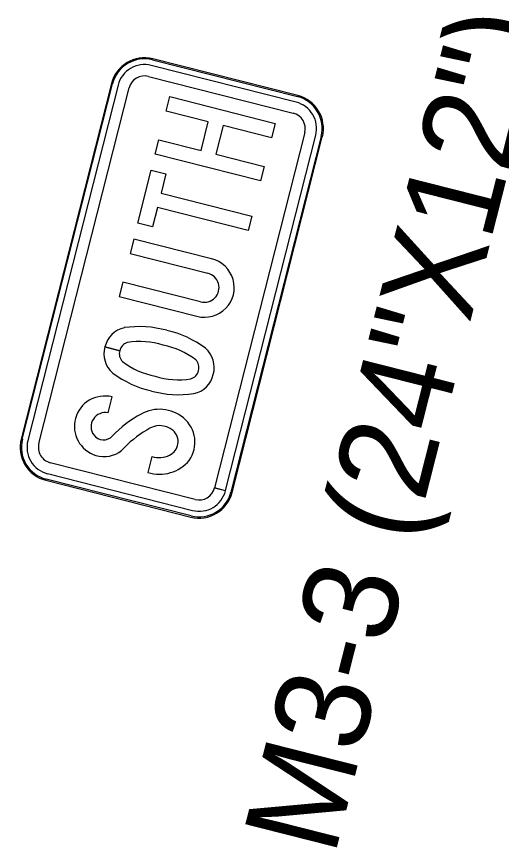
# Model space of a CAD drawing. Extents: x 670257 to 671518, y 737783 to 738188.
# Drawn here: x 670267.544 to 670268.827, y 738167.909 to 738170.109 of the extents above; entities that cross this region are included whole.
import ezdxf

# ---------------------------------------------------------------- set-up
doc = ezdxf.new("R2010")
doc.units = 0
doc.layers.add('R_SIGN_ANNOT', color=7, linetype='Continuous')
doc.layers.add('R_SIGN_HWY102', color=7, linetype='Continuous')

msp = doc.modelspace()

# ---------------------------------------------------------------- linework, layer by layer
at = {"layer": 'R_SIGN_HWY102'}
for p, q in [((670267.9, 738169.9798), (670267.8999, 738169.9798)), ((670268.2836, 738169.8825), (670267.9, 738169.9798)), ((670267.9036, 738169.9943), (670267.9036, 738169.9943)), ((670267.9036, 738169.9943), (670268.2873, 738169.897)), ((670268.288, 738169.8999), (670267.9044, 738169.9972)), ((670267.9044, 738169.9972), (670267.9044, 738169.9972)), ((670268.288, 738169.8999), (670267.9044, 738169.9972)), ((670267.9044, 738169.9972), (670267.9044, 738169.9972)), ((670267.8926, 738169.9507), (670267.8926, 738169.9507)), ((670267.8926, 738169.9507), (670268.2762, 738169.8534)), ((670267.7951, 738169.9321), (670267.5562, 738168.9903)), ((670267.7951, 738169.9321), (670267.5562, 738168.9903)), ((670267.5591, 738168.9896), (670267.798, 738169.9314)), ((670267.8125, 738169.9277), (670267.5737, 738168.9859)), ((670267.6027, 738168.9785), (670267.8416, 738169.9203)), ((670267.7951, 738169.9321), (670267.7951, 738169.9321)), ((670267.7951, 738169.9321), (670267.7951, 738169.9321)), ((670267.798, 738169.9314), (670267.798, 738169.9314)), ((670267.8125, 738169.9277), (670267.8125, 738169.9277)), ((670267.8416, 738169.9203), (670267.8416, 738169.9203)), ((670268.2873, 738169.897), (670268.2873, 738169.897)), ((670268.288, 738169.8999), (670268.288, 738169.8999)), ((670268.288, 738169.8999), (670268.288, 738169.8999)), ((670268.2836, 738169.8825), (670268.2836, 738169.8825)), ((670268.2762, 738169.8534), (670268.2762, 738169.8534)), ((670268.3066, 738169.8024), (670268.0678, 738168.8609)), ((670268.3066, 738169.8024), (670268.3066, 738169.8024)), ((670268.0968, 738168.8535), (670268.3356, 738169.795)), ((670268.3501, 738169.7913), (670268.1113, 738168.8496)), ((670268.1142, 738168.8488), (670268.353, 738169.7906)), ((670268.1142, 738168.8489), (670268.353, 738169.7906)), ((670268.3356, 738169.795), (670268.3356, 738169.795)), ((670268.3501, 738169.7913), (670268.3501, 738169.7913)), ((670268.353, 738169.7906), (670268.353, 738169.7906)), ((670268.353, 738169.7906), (670268.353, 738169.7906)), ((670267.8152, 738169.3674), (670268.0209, 738169.3152)), ((670267.8152, 738169.3674), (670268.0209, 738169.3152)), ((670267.8152, 738169.3674), (670268.0209, 738169.3152)), ((670267.8171, 738169.2242), (670267.7778, 738169.2342)), ((670267.7778, 738169.2342), (670267.8171, 738169.2242)), ((670267.8171, 738169.2242), (670267.7778, 738169.2342)), ((670267.7778, 738169.2342), (670267.8171, 738169.2242)), ((670267.7861, 738169.06), (670267.7967, 738169.1019)), ((670267.7861, 738169.06), (670267.7967, 738169.1019)), ((670267.7861, 738169.06), (670267.7967, 738169.1019)), ((670267.5562, 738168.9903), (670267.5562, 738168.9903)), ((670267.5562, 738168.9903), (670267.5562, 738168.9903)), ((670267.5591, 738168.9896), (670267.5591, 738168.9896)), ((670267.5737, 738168.9859), (670267.5737, 738168.9859)), ((670267.6027, 738168.9785), (670267.6027, 738168.9785)), ((670268.0167, 738168.8302), (670267.6331, 738168.9275)), ((670267.6331, 738168.9275), (670267.6331, 738168.9275)), ((670267.9022, 738168.944), (670267.8915, 738168.9014)), ((670267.9022, 738168.944), (670267.8915, 738168.9014)), ((670267.9022, 738168.944), (670267.8915, 738168.9014)), ((670267.6213, 738168.881), (670267.6213, 738168.881)), ((670267.6213, 738168.881), (670268.0049, 738168.7837)), ((670267.6213, 738168.881), (670267.6213, 738168.881)), ((670267.6213, 738168.881), (670268.0049, 738168.7837)), ((670268.0056, 738168.7866), (670267.622, 738168.884)), ((670267.622, 738168.884), (670267.622, 738168.8839)), ((670267.6257, 738168.8985), (670267.6257, 738168.8985)), ((670267.6257, 738168.8985), (670268.0093, 738168.8012)), ((670268.0967, 738168.8532), (670268.0677, 738168.8606)), ((670268.0677, 738168.8606), (670268.0677, 738168.8606)), ((670268.0678, 738168.8609), (670268.0968, 738168.8535)), ((670268.0967, 738168.8532), (670268.0967, 738168.8532)), ((670268.1142, 738168.8488), (670268.1113, 738168.8496)), ((670268.1113, 738168.8496), (670268.1113, 738168.8496)), ((670268.1113, 738168.8496), (670268.1142, 738168.8489)), ((670268.1142, 738168.8488), (670268.1142, 738168.8488)), ((670268.0167, 738168.8302), (670268.0167, 738168.8302)), ((670268.0093, 738168.8012), (670268.0093, 738168.8012)), ((670268.0049, 738168.7837), (670268.0049, 738168.7837)), ((670268.0049, 738168.7837), (670268.0049, 738168.7837)), ((670268.0056, 738168.7866), (670268.0056, 738168.7866))]:
    msp.add_line(p, q, dxfattribs=at)
for points in [[(670267.9108, 738169.7445), (670267.9206, 738169.7829), (670268.0322, 738169.7546), (670268.0513, 738169.8302), (670267.9398, 738169.8585), (670267.9495, 738169.897), (670268.2285, 738169.8263), (670268.2187, 738169.7878), (670268.0904, 738169.8203), (670268.0712, 738169.7447), (670268.1995, 738169.7122), (670268.1898, 738169.6737)], [(670267.9108, 738169.7445), (670267.9206, 738169.7829), (670268.0322, 738169.7546), (670268.0513, 738169.8302), (670267.9398, 738169.8585), (670267.9495, 738169.897), (670268.2285, 738169.8263), (670268.2187, 738169.7878), (670268.0904, 738169.8203), (670268.0712, 738169.7447), (670268.1995, 738169.7122), (670268.1898, 738169.6737)], [(670267.9108, 738169.7445), (670267.9206, 738169.7829), (670268.0322, 738169.7546), (670268.0513, 738169.8302), (670267.9398, 738169.8585), (670267.9495, 738169.897), (670268.2285, 738169.8263), (670268.2187, 738169.7878), (670268.0904, 738169.8203), (670268.0712, 738169.7447), (670268.1995, 738169.7122), (670268.1898, 738169.6737)], [(670267.9165, 738169.603), (670267.9036, 738169.5522), (670267.8646, 738169.5621), (670267.9001, 738169.7022), (670267.9392, 738169.6923), (670267.9263, 738169.6415), (670268.1662, 738169.5807), (670268.1564, 738169.5421)], [(670267.9165, 738169.603), (670267.9036, 738169.5522), (670267.8646, 738169.5621), (670267.9001, 738169.7022), (670267.9392, 738169.6923), (670267.9263, 738169.6415), (670268.1662, 738169.5807), (670268.1564, 738169.5421)], [(670267.9165, 738169.603), (670267.9036, 738169.5522), (670267.8646, 738169.5621), (670267.9001, 738169.7022), (670267.9392, 738169.6923), (670267.9263, 738169.6415), (670268.1662, 738169.5807), (670268.1564, 738169.5421)]]:
    msp.add_lwpolyline(points, close=True, dxfattribs=at)
for points in [[(670268.0596, 738169.4677), (670267.8539, 738169.5199), (670267.8441, 738169.4815), (670268.0498, 738169.4293)], [(670268.0596, 738169.4677), (670267.8539, 738169.5199), (670267.8441, 738169.4815), (670268.0498, 738169.4293)], [(670268.0596, 738169.4677), (670267.8539, 738169.5199), (670267.8441, 738169.4815), (670268.0498, 738169.4293)], [(670268.0307, 738169.3537), (670267.8249, 738169.4058), (670267.8152, 738169.3674)], [(670268.0307, 738169.3537), (670267.8249, 738169.4058), (670267.8152, 738169.3674)], [(670268.0307, 738169.3537), (670267.8249, 738169.4058), (670267.8152, 738169.3674)]]:
    msp.add_lwpolyline(points, dxfattribs=at)
for centre, major_axis, ratio, start_param, end_param in [((670267.8823, 738169.91), (0.0221, 0.0872), 0.999584, 0, 1.570796), ((670267.8823, 738169.91), (0.0221, 0.0872), 0.999584, 0, 1.570796), ((670267.8823, 738169.91), (0.0214, 0.0843), 0.999584, 0, 1.570796), ((670267.8823, 738169.91), (0.0177, 0.0698), 0.999584, 0, 1.570796), ((670267.8823, 738169.91), (0.0103, 0.0407), 0.999584, 0, 1.570796), ((670268.2659, 738169.8127), (0.0214, 0.0843), 0.999584, 4.712389, 6.283185), ((670268.2659, 738169.8127), (0.0221, 0.0872), 0.999584, 4.712389, 6.283185), ((670268.2659, 738169.8127), (0.0221, 0.0872), 0.999584, 4.712389, 6.283185), ((670268.2659, 738169.8127), (0.0177, 0.0698), 0.999584, 4.712389, 6.283185), ((670268.2659, 738169.8127), (0.0103, 0.0407), 0.999584, 4.712389, 6.283185), ((670268.0402, 738169.3915), (-0.0774, 0.0196), 0.985401, 1.570796, 4.712389), ((670268.0402, 738169.3915), (-0.0774, 0.0196), 0.985401, 1.570796, 4.712389), ((670268.0402, 738169.3915), (-0.0774, 0.0196), 0.985401, 1.570796, 4.712389), ((670268.0402, 738169.3915), (-0.0384, 0.0097), 0.985401, 1.570796, 4.712389), ((670268.0402, 738169.3915), (-0.0384, 0.0097), 0.985401, 1.570796, 4.712389), ((670268.0402, 738169.3915), (-0.0384, 0.0097), 0.985401, 1.570796, 4.712389), ((670267.8441, 738169.2197), (-0.0657, 0.0167), 0.987317, 5.182411, 6.318105), ((670267.8441, 738169.2197), (-0.0657, 0.0167), 0.987317, 5.182411, 6.317893), ((670267.8441, 738169.2197), (-0.0657, 0.0167), 0.987317, 5.182411, 6.317893), ((670267.87, 738169.0184), (-0.2645, 0.0671), 0.987317, 4.692766, 5.109028), ((670267.87, 738169.0184), (-0.2645, 0.0671), 0.987317, 4.692766, 5.109028), ((670267.87, 738169.0184), (-0.2645, 0.0671), 0.987317, 4.692766, 5.109028), ((670267.8804, 738169.0157), (-0.2645, 0.0671), 0.987317, 4.31575, 4.732012), ((670267.8804, 738169.0157), (-0.2645, 0.0671), 0.987317, 4.31575, 4.732012), ((670267.8804, 738169.0157), (-0.2645, 0.0671), 0.987317, 4.31575, 4.732012), ((670267.8429, 738169.2152), (-0.0657, 0.0167), 0.987317, 6.248265, 7.383959), ((670267.8429, 738169.2152), (-0.0657, 0.0167), 0.987317, 6.248265, 7.383959), ((670267.8429, 738169.2152), (-0.0657, 0.0167), 0.987317, 6.248265, 7.383959), ((670267.8455, 738169.2185), (-0.0281, 0.0071), 0.987317, 5.258281, 6.33678), ((670267.8455, 738169.2185), (-0.0281, 0.0071), 0.987317, 5.258281, 6.336283), ((670267.8455, 738169.2185), (-0.0281, 0.0071), 0.987317, 5.258281, 6.336283), ((670267.8702, 738169.0365), (-0.2078, 0.0527), 0.987317, 4.667051, 5.113562), ((670267.8702, 738169.0365), (-0.2078, 0.0527), 0.987317, 4.667051, 5.113562), ((670267.8702, 738169.0365), (-0.2078, 0.0527), 0.987317, 4.667051, 5.113562), ((670267.889, 738169.0318), (-0.2078, 0.0527), 0.987317, 4.311216, 4.757727), ((670267.889, 738169.0318), (-0.2078, 0.0527), 0.987317, 4.311216, 4.757727), ((670267.889, 738169.0318), (-0.2078, 0.0527), 0.987317, 4.311216, 4.757727), ((670267.9993, 738169.1804), (-0.0657, 0.0167), 0.987317, 3.106673, 4.242367), ((670267.9993, 738169.1804), (-0.0657, 0.0167), 0.987317, 3.106673, 4.242367), ((670267.9993, 738169.1804), (-0.0657, 0.0167), 0.987317, 3.106673, 4.242367), ((670267.8447, 738169.2156), (-0.0281, 0.0071), 0.987317, 6.22959, 7.30809), ((670267.8447, 738169.2156), (-0.0281, 0.0071), 0.987317, 6.22959, 7.30809), ((670267.8447, 738169.2156), (-0.0281, 0.0071), 0.987317, 6.22959, 7.30809), ((670267.9532, 738169.3638), (-0.2078, 0.0527), 0.987317, 1.169623, 1.616135), ((670267.9532, 738169.3638), (-0.2078, 0.0527), 0.987317, 1.169623, 1.616135), ((670267.9532, 738169.3638), (-0.2078, 0.0527), 0.987317, 1.169623, 1.616135), ((670267.9974, 738169.18), (-0.0281, 0.0071), 0.987317, 3.087997, 4.166497), ((670267.9974, 738169.18), (-0.0281, 0.0071), 0.987317, 3.087997, 4.166497), ((670267.9974, 738169.18), (-0.0281, 0.0071), 0.987317, 3.087997, 4.166497), ((670267.9617, 738169.3799), (-0.2645, 0.0671), 0.987317, 1.174158, 1.59042), ((670267.9617, 738169.3799), (-0.2645, 0.0671), 0.987317, 1.174158, 1.59042), ((670267.9617, 738169.3799), (-0.2645, 0.0671), 0.987317, 1.174158, 1.59042), ((670267.9967, 738169.177), (-0.0281, 0.0071), 0.987317, 2.116688, 3.195188), ((670267.9967, 738169.177), (-0.0281, 0.0071), 0.987317, 2.116688, 3.195188), ((670267.9967, 738169.177), (-0.0281, 0.0071), 0.987317, 2.116688, 3.195188), ((670267.972, 738169.3591), (-0.2078, 0.0527), 0.987317, 1.525458, 1.97197), ((670267.972, 738169.3591), (-0.2078, 0.0527), 0.987317, 1.525458, 1.97197), ((670267.972, 738169.3591), (-0.2078, 0.0527), 0.987317, 1.525458, 1.97197), ((670267.9981, 738169.1758), (-0.0657, 0.0167), 0.987317, 2.040819, 3.176513), ((670267.9981, 738169.1758), (-0.0657, 0.0167), 0.987317, 2.040819, 3.176513), ((670267.9981, 738169.1758), (-0.0657, 0.0167), 0.987317, 2.040819, 3.176513), ((670267.7788, 738169.0233), (-0.0796, 0.0202), 0.981581, 4.736267, 7.790596), ((670267.7788, 738169.0233), (-0.0796, 0.0202), 0.981581, 4.736267, 7.790596), ((670267.7788, 738169.0233), (-0.0796, 0.0202), 0.981581, 4.736267, 7.790596), ((670267.9721, 738169.3772), (-0.2645, 0.0671), 0.987317, 1.551173, 1.967435), ((670267.9721, 738169.3772), (-0.2645, 0.0671), 0.987317, 1.551173, 1.967435), ((670267.9721, 738169.3772), (-0.2645, 0.0671), 0.987317, 1.551173, 1.967435), ((670267.9228, 738168.9725), (-0.0951, 0.0241), 0.981581, 4.260987, 5.485755), ((670267.9228, 738168.9725), (-0.0951, 0.0241), 0.981581, 4.260987, 5.485755), ((670267.9228, 738168.9725), (-0.0951, 0.0241), 0.981581, 4.260987, 5.485755), ((670267.7796, 738169.0226), (-0.0374, 0.0095), 0.981581, 4.786904, 7.140738), ((670267.7796, 738169.0226), (-0.0374, 0.0095), 0.981581, 4.786904, 7.140738), ((670267.7796, 738169.0226), (-0.0374, 0.0095), 0.981581, 4.786904, 7.140738), ((670268.0205, 738168.794), (-0.2944, 0.0747), 0.981581, 5.462886, 5.782242), ((670268.0205, 738168.794), (-0.2944, 0.0747), 0.981581, 5.462886, 5.782242), ((670268.0205, 738168.794), (-0.2944, 0.0747), 0.981581, 5.462886, 5.782242), ((670267.9299, 738168.982), (-0.0835, 0.0212), 0.981581, 2.786047, 4.251692), ((670267.9299, 738168.982), (-0.0835, 0.0212), 0.981581, 2.786047, 4.251692), ((670267.9299, 738168.982), (-0.0835, 0.0212), 0.981581, 2.786047, 4.251692), ((670268.0581, 738168.7455), (-0.3108, 0.0788), 0.981581, 5.515137, 5.786988), ((670268.0581, 738168.7455), (-0.3108, 0.0788), 0.981581, 5.515137, 5.786988), ((670268.0581, 738168.7455), (-0.3108, 0.0788), 0.981581, 5.515137, 5.786988), ((670267.9226, 738168.9718), (-0.0531, 0.0135), 0.981581, 4.254409, 5.632398), ((670267.9226, 738168.9718), (-0.0531, 0.0135), 0.981581, 4.254409, 5.632398), ((670267.9226, 738168.9718), (-0.0531, 0.0135), 0.981581, 4.254409, 5.632398), ((670267.9313, 738168.9833), (-0.0389, 0.0099), 0.981581, 2.261787, 4.23006), ((670267.9313, 738168.9833), (-0.0389, 0.0099), 0.981581, 2.261787, 4.23006), ((670267.9313, 738168.9833), (-0.0389, 0.0099), 0.981581, 2.261787, 4.23006), ((670267.6434, 738168.9682), (0.0221, 0.0872), 0.999584, 1.570796, 3.141593), ((670267.6434, 738168.9682), (0.0221, 0.0872), 0.999584, 1.570796, 3.141593), ((670267.6434, 738168.9682), (0.0214, 0.0843), 0.999584, 1.570796, 3.141593), ((670267.7738, 738169.0193), (-0.0309, 0.0078), 0.981581, 0.87378, 2.656959), ((670267.7738, 738169.0193), (-0.0309, 0.0078), 0.981581, 0.87378, 2.656959), ((670267.7738, 738169.0193), (-0.0309, 0.0078), 0.981581, 0.87378, 2.656959), ((670267.6434, 738168.9682), (0.0177, 0.0698), 0.999584, 1.570796, 3.141593), ((670267.6434, 738168.9682), (0.0103, 0.0407), 0.999584, 1.570796, 3.141593), ((670267.7743, 738169.016), (-0.0715, 0.0181), 0.981581, 1.534831, 2.511766), ((670267.7743, 738169.016), (-0.0715, 0.0181), 0.981581, 1.534831, 2.511766), ((670267.7743, 738169.016), (-0.0715, 0.0181), 0.981581, 1.534831, 2.511766), ((670267.9202, 738169.0031), (-0.0611, 0.0155), 0.981581, 1.524757, 2.28214), ((670267.9202, 738169.0031), (-0.0611, 0.0155), 0.981581, 1.524757, 2.28214), ((670267.9202, 738169.0031), (-0.0611, 0.0155), 0.981581, 1.524757, 2.28214), ((670267.9208, 738168.9986), (-0.1003, 0.0254), 0.981581, 1.526364, 2.701682), ((670267.9208, 738168.9986), (-0.1003, 0.0254), 0.981581, 1.526364, 2.701682), ((670267.9208, 738168.9986), (-0.1003, 0.0254), 0.981581, 1.526364, 2.701682), ((670268.027, 738168.8709), (0.0103, 0.0407), 0.999584, 3.141593, 4.712389), ((670268.027, 738168.8709), (0.0221, 0.0872), 0.999584, 3.141593, 4.712389), ((670268.027, 738168.8709), (0.0221, 0.0872), 0.999584, 3.141593, 4.712389), ((670268.027, 738168.8709), (0.0214, 0.0843), 0.999584, 3.141593, 4.712389), ((670268.027, 738168.8709), (0.0177, 0.0698), 0.999584, 3.141593, 4.712389)]:
    msp.add_ellipse(centre, major_axis=major_axis, ratio=ratio, start_param=start_param, end_param=end_param, dxfattribs=at)

# ---------------------------------------------------------------- texts
at = {"layer": 'R_SIGN_ANNOT'}
msp.add_text('M3-3 (24"X12")', height=0.25, rotation=75.7686, dxfattribs=at).set_placement((670268.3848, 738167.8821))

doc.saveas('drawing.dxf')
